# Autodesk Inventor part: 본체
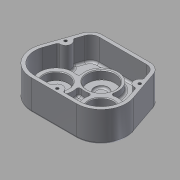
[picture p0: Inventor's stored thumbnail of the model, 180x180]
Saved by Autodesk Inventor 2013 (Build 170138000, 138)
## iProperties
Created: 2014-12
Part Number: 본체
Material: 알루미늄 6061
Document SubType Name: Modeling
Designer: Administrator
Density: 2.71 g/cm^3
Mass: 613.43 g
Surface Area: 665.343 cm^2
Volume: 226.358 cm^3
Author: Administrator
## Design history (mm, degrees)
sketch "스케치1"
  geometry: L1 (-34.162, 36)-(34.162, 36); L2 (0, 0)-(46, 0); L3 (0, 0)-(32.527, -32.527); L4 (0, 0)-(-32.527, -32.527); L5 (-32.527, -68.527)-(32.527, -68.527); L6 (51.181, 23.862)-(66.565, -20.803); L7 (-51.181, 23.862)-(-66.565, -20.803); A1 r 46 centre (0, 0) between (46, 0) and (32.527, -32.527); A2 r 36 centre (32.527, -32.527) between (32.527, -68.527) and (66.565, -20.803); A3 r 36 centre (-32.527, -32.527) between (-66.565, -20.803) and (-32.527, -68.527); A4 r 18 centre (-34.162, 18) between (-34.162, 36) and (-51.181, 23.862); A5 r 18 centre (34.162, 18) between (51.181, 23.862) and (34.162, 36); 3 further points
  constraints: 14 end point, 11 point on circle, 8 tangent, 5 centre point, 4 point on line, 3 coincident, 1 equal radius, 1 horizontal, 1 parallel, 1 perpendicular
  dimensions: "d1" = 94 distance of point (-47, 36) point (47, 36); "d3" = 47 horizontal distance of point (0, 0) point (47, 36); "d4" = 92 diameter of A1; "d5" = 36 distance from line of point (0, 0) L1; "d6" = 45 deg angle of L3 L2; "d8" = 72 diameter of A3; "d9" = 18 radius of A4; "d10" = 36 radius of A2
extrude "돌출1" new body sketch "스케치1" distance "d11" = 44; taper "d12" = 0 deg
sketch "스케치2"
  geometry: L1 (-32.527, -68.527)-(32.527, -68.527) reference; L2 (66.565, -20.803)-(51.181, 23.862) reference; L3 (-32.527, -68.527)-(32.527, -68.527) reference; L4 (66.565, -20.803)-(51.181, 23.862) reference; L5 (34.162, 36)-(-34.162, 36) reference; L6 (-51.181, 23.862)-(-66.565, -20.803) reference; L7 (-36.272, -63.527)-(32.527, -63.527); L8 (-34.162, 31)-(34.162, 31); L9 (61.837, -22.432)-(46.453, 22.233); L10 (-46.453, 22.233)-(-61.837, -22.432); A1 r 36 centre (32.527, -32.527) between (32.527, -68.527) and (66.565, -20.803) reference; A2 r 18 centre (-34.162, 18) between (-34.162, 36) and (-51.181, 23.862) reference; A3 r 36 centre (-32.527, -32.527) between (-66.565, -20.803) and (-32.527, -68.527) reference; A4 r 36 centre (32.527, -32.527) between (32.527, -68.527) and (66.565, -20.803) reference; A5 r 18 centre (34.162, 18) between (51.181, 23.862) and (34.162, 36) reference; A6 r 18 centre (-34.162, 18) between (-34.162, 36) and (-51.181, 23.862) reference; A7 r 36 centre (-32.527, -32.527) between (-66.565, -20.803) and (-32.527, -68.527) reference; A8 r 13 centre (-34.162, 18) between (-34.162, 31) and (-46.453, 22.233); A9 r 13 centre (34.162, 18) between (46.453, 22.233) and (34.162, 31); A10 r 31 centre (32.527, -32.527) between (32.527, -63.527) and (61.837, -22.432); A11 r 31 centre (-32.527, -32.527) between (-61.837, -22.432) and (-32.527, -63.527); 1 further point
  constraints: 8 end point, 8 point on circle, 7 tangent, 4 centre point, 4 coincident, 1 parallel, 1 point on line
  dimensions: "d17" = 13 radius of A8; "d18" = 13 radius of A9; "d19" = 31 radius of A10; "d20" = 31 radius of A11
extrude "돌출2" cut sketch "스케치2" distance "d21" = 34; taper "d22" = 0 deg
sketch "스케치3"
  geometry: L1 (-61.837, -22.432)-(-46.453, 22.233) reference; L2 (32.527, -63.527)-(-32.527, -63.527) reference; L3 (46.453, 22.233)-(61.837, -22.432) reference; L4 (-34.162, 31)-(34.162, 31) reference; L5 (-50.817, 9.564)-(-56.027, -5.564); L6 (-8, -63.527)-(8, -63.527); L7 (56.027, -5.564)-(50.817, 9.564); A1 r 8 centre (53.422, 2) between (50.817, 9.564) and (56.027, -5.564); A2 r 8 centre (-53.422, 2) between (-56.027, -5.564) and (-50.817, 9.564); A3 r 8 centre (0, -63.527) between (8, -63.527) and (-8, -63.527); 1 further point
  constraints: 8 point on line, 6 end point, 6 point on circle, 3 centre point, 3 collinear, 1 midpoint
  dimensions: "d23" = 8 radius of A1; "d24" = 29 distance from line of A1.centre L4; "d25" = 8 radius of A2; "d26" = 29 distance from line of A2.centre L4; "d27" = 8 radius of A3
extrude "돌출3" join sketch "스케치3" distance "d28" = 34; taper "d29" = 0 deg
sketch "스케치4"
  geometry: A1 r 8 centre (-53.422, 2) between (-56.027, -5.564) and (-50.817, 9.564) reference; A2 r 8 centre (53.422, 2) between (50.817, 9.564) and (56.027, -5.564) reference; A3 r 8 centre (0, -63.527) between (8, -63.527) and (-8, -63.527) reference; 4 further points
  constraints: 3 coincident
hole "구멍1" sketch "스케치4" at (-53.422, 2), (0, -63.527), (53.422, 2) diameter "d30" = 4.134; stored, may be unused: countersink angle "d34" = 82 deg, drill point angle "d36" = 118 deg; dims "d31" = 20, "d32" = 3.023, "d33" = 2, "d35" = 23
sketch "스케치5"
  geometry: C1 r 24 at (0, 0); C2 r 24 at (-32.527, -32.527); C3 r 24 at (32.527, -32.527); A1 r 31 centre (-32.527, -32.527) between (-61.837, -22.432) and (-32.527, -63.527) reference; A2 r 31 centre (32.527, -32.527) between (32.527, -63.527) and (61.837, -22.432) reference; 1 further point
  constraints: 3 centre point, 3 coincident
  dimensions: "d37" = 48 diameter of C1; "d38" = 48 diameter of C2; "d39" = 48 diameter of C3
extrude "돌출4" join sketch "스케치5" distance "d40" = 11; taper "d41" = 0 deg
sketch "스케치6"
  geometry: C1 r 20 at (0, 0); A1 r 24 centre (0, 0) between (21.111, -11.416) and (-21.111, -11.416) reference
  constraints: 1 centre point, 1 coincident
  dimensions: "d42" = 40 diameter of C1
extrude "돌출5" cut sketch "스케치6" distance "d43" = 12; taper "d44" = 0 deg
sketch "스케치7"
  geometry: C1 r 20 at (0, 0) reference; C2 r 10 at (0, 0)
  constraints: 1 centre point, 1 coincident
  dimensions: "d45" = 20 diameter of C2
extrude "돌출6" cut sketch "스케치7" distance "d46" = 3; taper "d47" = 0 deg
sketch "스케치8"
  geometry: C1 r 17.5 at (-32.527, -32.527); C2 r 17.5 at (32.527, -32.527); A1 r 24 centre (32.527, -32.527) between (11.416, -21.111) and (21.111, -11.416) reference; A2 r 24 centre (-32.527, -32.527) between (-21.111, -11.416) and (-11.416, -21.111) reference
  constraints: 2 centre point, 2 coincident
  dimensions: "d48" = 35 diameter of C1; "d49" = 35 diameter of C2
extrude "돌출7" cut sketch "스케치8" distance "d50" = 11; taper "d51" = 0 deg
sketch "스케치9"
  geometry: C1 r 7.75 at (-32.527, -32.527); C2 r 7.75 at (32.527, -32.527); A1 r 31 centre (-32.527, -32.527) between (-61.837, -22.432) and (-32.527, -63.527) reference; A2 r 31 centre (32.527, -32.527) between (32.527, -63.527) and (61.837, -22.432) reference
  constraints: 2 centre point, 2 coincident
  dimensions: "d52" = 15.5 diameter of C1; "d53" = 15.5 diameter of C2
extrude "돌출8" cut sketch "스케치9" distance "d54" = 10; taper "d55" = 0 deg
sketch "스케치10"
  geometry: C1 r 7.75 at (32.527, -32.527) reference; C2 r 7.75 at (-32.527, -32.527) reference; C3 r 20 at (-32.527, -32.527); C4 r 20 at (32.527, -32.527); A1 r 36 centre (32.527, -32.527) between (32.527, -68.527) and (66.565, -20.803) reference; A2 r 36 centre (-32.527, -32.527) between (-66.565, -20.803) and (-32.527, -68.527) reference; 1 further point
  constraints: 2 centre point, 2 coincident
  dimensions: "d56" = 40 diameter of C3; "d57" = 40 diameter of C4
extrude "돌출9" join sketch "스케치10" distance "d58" = 7; taper "d59" = -10 deg
sketch "스케치11"
  geometry: L1 (34.162, 36)-(-34.162, 36) reference; 2 further points
  constraints: 1 vertical alignment, 1 other
  dimensions: "d63" = 30 distance from line of point (0, 6) L1
feature "엠보싱1" sketch "스케치11" dims "d1" = 94, "d3" = 47, "d4" = 92, "d5" = 36, "d6" = 45 deg, "d8" = 72, "d9" = 18, "d10" = 36, "d61" = 1, "d62" = 0
fillet "모깎기1" dims "d64" = 0.3
sketch "스케치12"
  geometry: C1 r 18.766 at (0, 0) reference; C2 r 18.766 at (65.054, 0) reference; C3 r 20 at (65.054, 0) reference; C4 r 15 at (0, 0); C5 r 15 at (65.054, 0); 1 further point
  constraints: 2 centre point, 2 coincident
  dimensions: "d65" = 30 diameter of C4; "d66" = 30 diameter of C5
extrude "돌출10" cut sketch "스케치12" distance "d67" = 7; taper "d68" = 0 deg
fillet "모깎기2" dims "d69" = 0.1
fillet "모깎기3" dims "d70" = 3
fillet "모깎기4" dims "d71" = 3
fillet "모깎기5" dims "d72" = 3
fillet "모깎기6" dims "d73" = 3
fillet "모깎기7" dims "d74" = 3
chamfer "모따기1" distance "d75" = 1; stored, may be unused: second distance "d76" = 2, angle "d77" = 45 deg
fillet "모깎기8" dims "d78" = 3
fillet "모깎기9" dims "d79" = 0.3
node "솔리드1"
node "투영된 루프1"
node "투영된 루프2"
